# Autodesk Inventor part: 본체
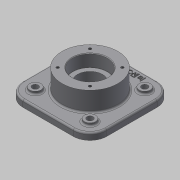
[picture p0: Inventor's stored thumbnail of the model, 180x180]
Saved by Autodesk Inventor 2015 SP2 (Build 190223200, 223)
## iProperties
Created: 2015-07
Part Number: 본체
Material: 일반
Document SubType Name: Modeling
Designer: AMC
Density: 1 g/cm^3
Appearance: 기본값
Mass: 540.471 g
Surface Area: 800.934 cm^2
Volume: 540.471 cm^3
Author: AMC
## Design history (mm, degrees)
sketch "스케치2"
  geometry: L1 (-75, 75)-(75, 75); L2 (75, 75)-(75, -75); L3 (75, -75)-(-75, -75); L4 (-75, -75)-(-75, 75); L5 (-75, 75)-(75, -75); L6 (75, 75)-(-75, -75); 1 further point
  constraints: 12 end point, 2 midpoint, 2 parallel, 1 horizontal, 1 perpendicular
  dimensions: "d2" = 150 distance of L2.end L3.end; "d3" = 150 distance of L1.end L2.end
extrude "돌출1" new body sketch "스케치2" distance "d4" = 12; taper "d5" = 0 deg
fillet "모깎기1" dims "d6" = 30
sketch "스케치3"
  geometry: C1 r 50 at (0, 0); 1 further point
  constraints: 1 centre point, 1 coincident
  dimensions: "d8" = 100 diameter of C1
sketch "스케치4"
  geometry: C1 r 50 at (0, 0); 1 further point
  constraints: 1 centre point, 1 coincident
  dimensions: "d9" = 100 diameter of C1
extrude "돌출2" join sketch "스케치4" distance "d10" = 23; taper "d11" = 0 deg
extrude "돌출3" join sketch "스케치3" distance "d12" = 35; taper "d13" = 0 deg
sketch "스케치5"
  geometry: L1 (49, 49)-(-49, 49); L2 (-49, 49)-(-49, -49); L3 (-49, -49)-(49, -49); L4 (49, -49)-(49, 49); L5 (49, 49)-(-49, -49); L6 (-49, 49)-(49, -49); C1 r 10 at (49, 49); C2 r 10 at (49, -49); C3 r 10 at (-49, 49); C4 r 10 at (-49, -49); 1 further point
  constraints: 12 end point, 4 centre point, 4 coincident, 2 midpoint, 2 parallel, 1 horizontal, 1 perpendicular
  dimensions: "d14" = 98 distance of L3.end L2.end; "d15" = 98 distance of L2.end L1.end; "d16" = 20 diameter of C1; "d17" = 20 diameter of C2; "d18" = 20 diameter of C3; "d19" = 20 diameter of C4
extrude "돌출4" join sketch "스케치5" distance "d20" = 5; taper "d21" = 0 deg
hole "구멍1" diameter "d24" = 45; stored, may be unused: countersink angle "d28" = 90 deg, drill point angle "d30" = 118 deg; dims "d22" = 10, "d23" = 10, "d25" = 6, "d26" = 62, "d27" = 22, "d29" = 8
hole "구멍2" diameter "d33" = 45; stored, may be unused: countersink angle "d37" = 90 deg, drill point angle "d39" = 118 deg; dims "d31" = 10, "d32" = 10, "d34" = 6, "d35" = 62, "d36" = 22, "d38" = 8
hole "구멍3" diameter "d42" = 11; stored, may be unused: countersink angle "d46" = 90 deg, drill point angle "d48" = 118 deg; dims "d40" = 10, "d41" = 10, "d43" = 6, "d44" = 62, "d45" = 22, "d47" = 8
hole "구멍4" diameter "d51" = 11; stored, may be unused: countersink angle "d55" = 90 deg, drill point angle "d57" = 118 deg; dims "d49" = 10, "d50" = 10, "d52" = 6, "d53" = 62, "d54" = 22, "d56" = 8
hole "구멍5" diameter "d60" = 11; stored, may be unused: countersink angle "d64" = 90 deg, drill point angle "d66" = 118 deg; dims "d58" = 10, "d59" = 10, "d61" = 6, "d62" = 62, "d63" = 22, "d65" = 8
hole "구멍6" diameter "d69" = 11; stored, may be unused: countersink angle "d73" = 90 deg, drill point angle "d75" = 118 deg; dims "d67" = 10, "d68" = 10, "d70" = 6, "d71" = 62, "d72" = 22, "d74" = 8
fillet "모깎기2" dims "d76" = 3
fillet "모깎기3" dims "d77" = 0.3
chamfer "모따기1" distance "d78" = 1; stored, may be unused: second distance "d79" = 2, angle "d80" = 45 deg
sketch "스케치6"
  geometry: L1 (-32.5, 67.991)-(33.866, 67.991); L2 (33.866, 67.991)-(33.866, 58.384); L3 (33.866, 58.384)-(-32.5, 58.384); L4 (-32.5, 58.384)-(-32.5, 67.991); 1 further point
  constraints: 2 other
feature "엠보싱1" sketch "스케치6" dims "d2" = 150, "d3" = 150, "d81" = 1, "d82" = 0
sketch "스케치7"
  geometry: L1 (0, 0)-(41, 0); L2 (0, 0)-(28.991, 28.991); A1 r 41 centre (0, 0) between (41, 0) and (28.991, 28.991); 1 further point
  constraints: 4 end point, 2 point on circle, 1 centre point, 1 coincident, 1 horizontal
  dimensions: "d83" = 82 diameter of A1; "d84" = 45 deg angle of L1 L2
hole "구멍7" sketch "스케치7" at (28.991, 28.991) diameter "d85" = 4.917; stored, may be unused: countersink angle "d89" = 90 deg, drill point angle "d91" = 118 deg; dims "d86" = 10, "d87" = 4, "d88" = 2, "d90" = 13
sketch "스케치8"
  geometry: L1 (0, 0)-(41, 0); L2 (0, 0)-(28.991, 28.991); A1 r 41 centre (0, 0) between (41, 0) and (28.991, 28.991); 1 further point
  constraints: 4 end point, 2 point on circle, 1 centre point, 1 coincident, 1 horizontal
  dimensions: "d95" = 82 diameter of A1; "d96" = 45 deg angle of L1 L2
hole "구멍8" sketch "스케치8" at (28.991, 28.991) diameter "d97" = 4.917; stored, may be unused: countersink angle "d101" = 90 deg, drill point angle "d103" = 118 deg; dims "d98" = 10, "d99" = 4, "d100" = 2, "d102" = 13
node "솔리드1"
pattern_circular "원형 패턴1" dims angle "d93" = 360 deg
pattern_circular "원형 패턴2" dims angle "d105" = 360 deg
